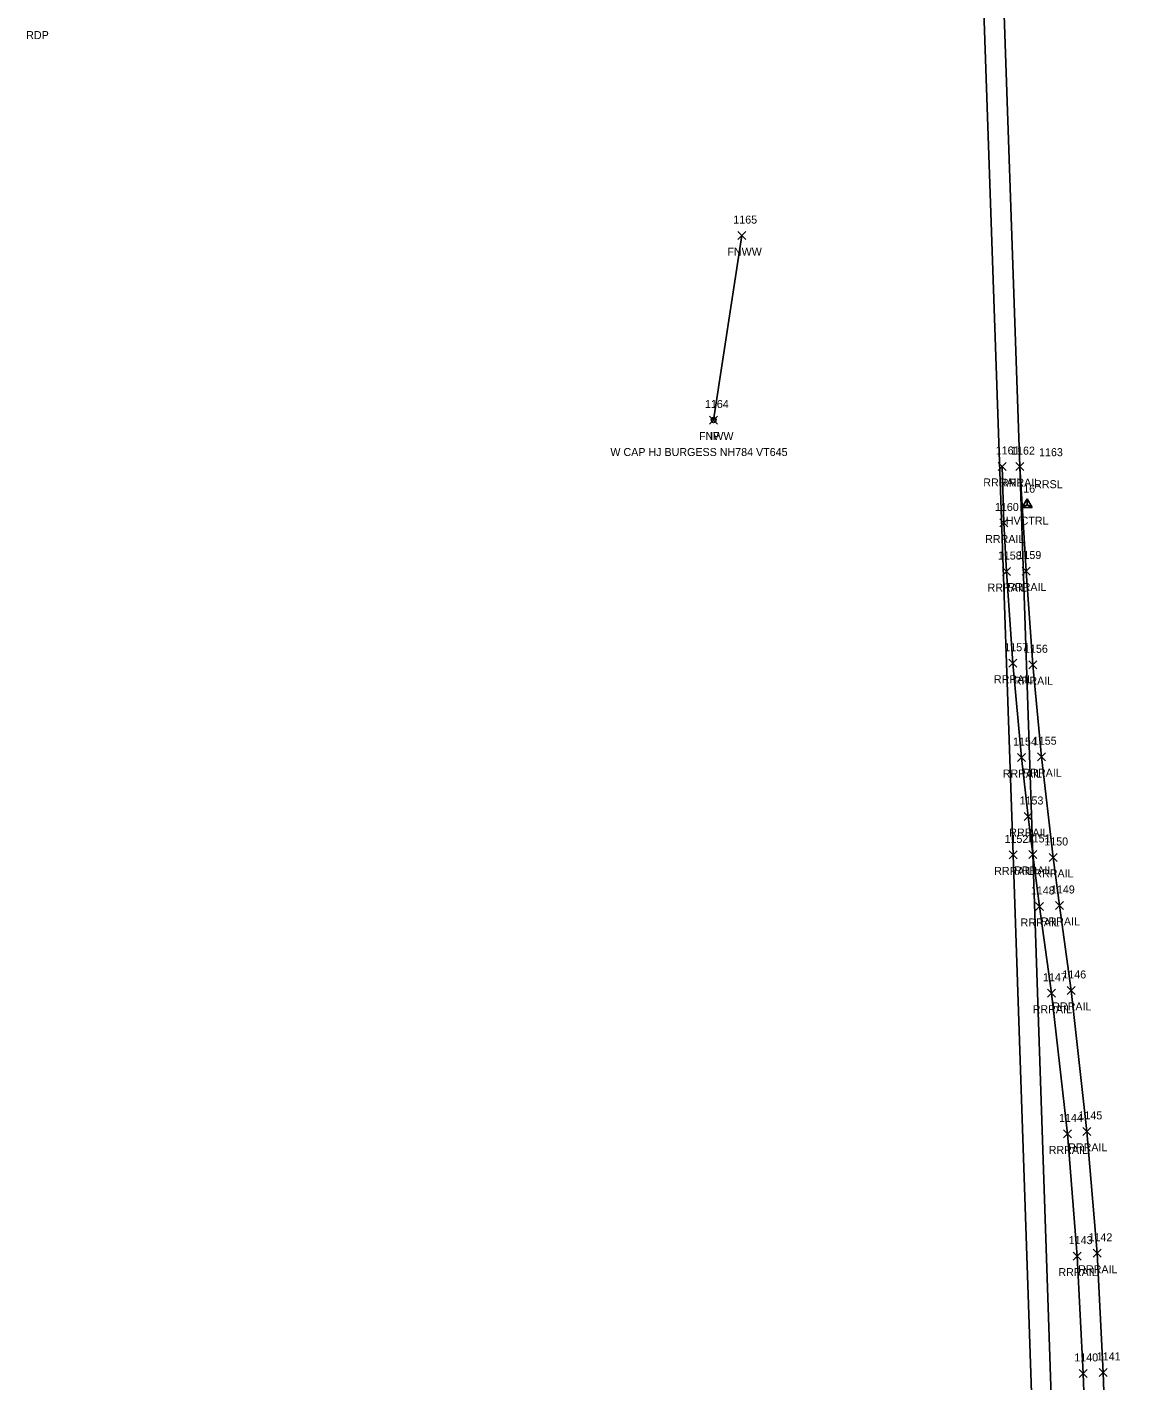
# Model space of a CAD drawing. Extents: x 1754529 to 1755810, y 621660 to 624656.
# Drawn here: x 1755390 to 1755667.2, y 622000 to 622338.3 of the extents above; entities that cross this region are included whole.
import ezdxf

# ---------------------------------------------------------------- set-up
doc = ezdxf.new("R2010")
doc.units = 0
for name, color, linetype in [('C_A', 7, 'Continuous'), ('C_I', 7, 'Continuous'), ('CPSM', 7, 'Continuous'), ('L_A', 7, 'Continuous'), ('L_I', 7, 'Continuous'), ('L_TIC', 7, 'Continuous'), ('LFNC', 7, 'Continuous'), ('M_A', 7, 'Continuous'), ('M_C', 7, 'Continuous'), ('M_I', 7, 'Continuous'), ('MPIR', 7, 'Continuous'), ('P_A', 7, 'Continuous'), ('R_A', 7, 'Continuous'), ('R_I', 7, 'Continuous'), ('R_TIC', 7, 'Continuous'), ('RR', 7, 'Continuous')]:
    doc.layers.add(name, color=color, linetype=linetype)

msp = doc.modelspace()

# ---------------------------------------------------------------- linework, layer by layer
at = {"layer": 'CPSM'}
for p, q in [((1755638.69, 622218.24), (1755639.94, 622220.41)), ((1755641.19, 622218.24), (1755639.94, 622220.41)), ((1755639.94, 622218.96), (1755639.94, 622220.41)), ((1755638.69, 622218.24), (1755639.94, 622218.96)), ((1755638.69, 622218.24), (1755641.19, 622218.24)), ((1755639.94, 622218.96), (1755639.94, 622218.96)), ((1755639.94, 622218.96), (1755641.19, 622218.24))]:
    msp.add_line(p, q, dxfattribs=at)
at = {"layer": 'L_TIC'}
for points in [[(1755567.69, 622285.2), (1755569.69, 622287.2)], [(1755569.69, 622285.2), (1755567.69, 622287.2)], [(1755560.6, 622239.12), (1755562.6, 622241.12)], [(1755562.6, 622239.12), (1755560.6, 622241.12)]]:
    msp.add_lwpolyline(points, dxfattribs=at)
at = {"layer": 'LFNC'}
msp.add_lwpolyline([(1755561.6, 622240.12), (1755568.69, 622286.2)], dxfattribs=at)
at = {"layer": 'MPIR'}
for radius in [0.625, 0.0833]:
    msp.add_circle((1755561.6, 622240.12), radius, dxfattribs=at)
at = {"layer": 'R_TIC'}
for points in [[(1755632.72, 622227.52), (1755634.72, 622229.52)], [(1755634.72, 622227.52), (1755632.72, 622229.52)], [(1755637.13, 622227.47), (1755639.13, 622229.47)], [(1755639.13, 622227.47), (1755637.13, 622229.47)], [(1755637.13, 622227.47), (1755639.13, 622229.47)], [(1755639.13, 622227.47), (1755637.13, 622229.47)], [(1755633.18, 622213.39), (1755635.18, 622215.39)], [(1755635.18, 622213.39), (1755633.18, 622215.39)], [(1755633.79, 622201.25), (1755635.79, 622203.25)], [(1755635.79, 622201.25), (1755633.79, 622203.25)], [(1755638.7, 622201.38), (1755640.7, 622203.38)], [(1755640.7, 622201.38), (1755638.7, 622203.38)], [(1755635.38, 622178.34), (1755637.38, 622180.34)], [(1755637.38, 622178.34), (1755635.38, 622180.34)], [(1755640.37, 622177.94), (1755642.37, 622179.94)], [(1755642.37, 622177.94), (1755640.37, 622179.94)], [(1755637.59, 622154.76), (1755639.59, 622156.76)], [(1755639.59, 622154.76), (1755637.59, 622156.76)], [(1755642.53, 622154.97), (1755644.53, 622156.97)], [(1755644.53, 622154.97), (1755642.53, 622156.97)], [(1755639.21, 622140.03), (1755641.21, 622142.03)], [(1755641.21, 622140.03), (1755639.21, 622142.03)], [(1755635.45, 622130.43), (1755637.45, 622132.43)], [(1755637.45, 622130.43), (1755635.45, 622132.43)], [(1755640.42, 622130.55), (1755642.42, 622132.55)], [(1755642.42, 622130.55), (1755640.42, 622132.55)], [(1755640.42, 622130.55), (1755642.42, 622132.55)], [(1755642.42, 622130.55), (1755640.42, 622132.55)], [(1755645.48, 622129.79), (1755647.48, 622131.79)], [(1755647.48, 622129.79), (1755645.48, 622131.79)], [(1755642.03, 622117.54), (1755644.03, 622119.54)], [(1755644.03, 622117.54), (1755642.03, 622119.54)], [(1755647.07, 622117.8), (1755649.07, 622119.8)], [(1755649.07, 622117.8), (1755647.07, 622119.8)], [(1755649.95, 622096.56), (1755651.95, 622098.56)], [(1755651.95, 622096.56), (1755649.95, 622098.56)], [(1755645.07, 622095.87), (1755647.07, 622097.87)], [(1755647.07, 622095.87), (1755645.07, 622097.87)], [(1755649.07, 622060.71), (1755651.07, 622062.71)], [(1755651.07, 622060.71), (1755649.07, 622062.71)], [(1755653.93, 622061.34), (1755655.93, 622063.34)], [(1755655.93, 622061.34), (1755653.93, 622063.34)], [(1755651.5, 622030.16), (1755653.5, 622032.16)], [(1755653.5, 622030.16), (1755651.5, 622032.16)], [(1755656.45, 622030.87), (1755658.45, 622032.87)], [(1755658.45, 622030.87), (1755656.45, 622032.87)], [(1755652.99, 622000.85), (1755654.99, 622002.85)], [(1755654.99, 622000.85), (1755652.99, 622002.85)], [(1755657.94, 622001.1), (1755659.94, 622003.1)], [(1755659.94, 622001.1), (1755657.94, 622003.1)]]:
    msp.add_lwpolyline(points, dxfattribs=at)
at = {"layer": 'RR'}
for points in [[(1755648.95, 621764.81), (1755636.45, 622131.43), (1755613.67, 622787.88), (1755609.16, 622923.97), (1755607.65, 622970.2), (1755606.39, 623016.18), (1755605.63, 623052.66), (1755604.97, 623087.09), (1755604.49, 623127.28), (1755604.22, 623170.71)], [(1755653.84, 621764.86), (1755641.42, 622131.55), (1755638.13, 622228.47), (1755618.69, 622787.98), (1755614.09, 622923.65), (1755612.57, 622970.4), (1755611.33, 623016.44), (1755610.51, 623052.88), (1755609.89, 623087.03), (1755609.4, 623127.16), (1755609.16, 623170.67)], [(1755662.28, 621764.64), (1755655.09, 621972.73), (1755653.99, 622001.85), (1755652.5, 622031.16), (1755650.07, 622061.71), (1755646.07, 622096.87), (1755643.03, 622118.54), (1755641.42, 622131.55), (1755640.21, 622141.03), (1755638.59, 622155.76), (1755636.38, 622179.34), (1755634.79, 622202.25), (1755634.18, 622214.39), (1755633.72, 622228.52)], [(1755667.17, 621764.34), (1755659.97, 621973.23), (1755658.94, 622002.1), (1755657.45, 622031.87), (1755654.93, 622062.34), (1755650.95, 622097.56), (1755648.07, 622118.8), (1755646.48, 622130.79), (1755643.53, 622155.97), (1755641.37, 622178.94), (1755639.7, 622202.38), (1755638.13, 622228.47)]]:
    msp.add_lwpolyline(points, dxfattribs=at)

# ---------------------------------------------------------------- texts
at = {"layer": 'C_A'}
msp.add_text('HVCTRL', height=2, dxfattribs=at).set_placement((1755634.63, 622213.96))
at = {"layer": 'C_I'}
msp.add_text('16', height=2, dxfattribs=at).set_placement((1755638.99, 622221.96))
at = {"layer": 'L_A'}
for p in [(1755565.04, 622281.2), (1755557.95, 622235.12)]:
    msp.add_text('FNWW', height=2, dxfattribs=at).set_placement(p)
at = {"layer": 'L_I'}
for s, p in [('1165', (1755566.52, 622289.2)), ('1164', (1755559.43, 622243.12))]:
    msp.add_text(s, height=2, dxfattribs=at).set_placement(p)
at = {"layer": 'M_A'}
msp.add_text('IP', height=2, dxfattribs=at).set_placement((1755560.65, 622235.12))
at = {"layer": 'M_C'}
msp.add_text('W CAP HJ BURGESS NH784 VT645', height=2, dxfattribs=at).set_placement((1755535.79, 622231.12))
at = {"layer": 'M_I'}
msp.add_text('1164', height=2, dxfattribs=at).set_placement((1755559.43, 622243.12))
at = {"layer": 'P_A'}
msp.add_text('RDP', height=2, dxfattribs=at).set_placement((1755389.75, 622335.32))
at = {"layer": 'R_A'}
for s, p in [('RRRAIL', (1755629.01, 622223.52)), ('RRRAIL', (1755633.42, 622223.47)), ('RRRAIL', (1755633.42, 622223.47)), ('RRSL', (1755641.72, 622223.08)), ('RRRAIL', (1755629.47, 622209.39)), ('RRRAIL', (1755630.08, 622197.25)), ('RRRAIL', (1755634.99, 622197.38)), ('RRRAIL', (1755631.67, 622174.34)), ('RRRAIL', (1755636.66, 622173.94)), ('RRRAIL', (1755633.88, 622150.76)), ('RRRAIL', (1755638.82, 622150.97)), ('RRRAIL', (1755635.5, 622136.03)), ('RRRAIL', (1755631.74, 622126.43)), ('RRRAIL', (1755636.71, 622126.55)), ('RRRAIL', (1755636.71, 622126.55)), ('RRRAIL', (1755641.77, 622125.79)), ('RRRAIL', (1755638.33, 622113.54)), ('RRRAIL', (1755643.36, 622113.8)), ('RRRAIL', (1755641.36, 622091.87)), ('RRRAIL', (1755646.24, 622092.56)), ('RRRAIL', (1755645.36, 622056.71)), ('RRRAIL', (1755650.23, 622057.34)), ('RRRAIL', (1755647.79, 622026.16)), ('RRRAIL', (1755652.74, 622026.87))]:
    msp.add_text(s, height=2, dxfattribs=at).set_placement(p)
at = {"layer": 'R_I'}
for s, p in [('1161', (1755632.11, 622231.52)), ('1162', (1755635.96, 622231.47)), ('1162', (1755635.96, 622231.47)), ('1163', (1755642.95, 622231.08)), ('1160', (1755631.92, 622217.39)), ('1158', (1755632.66, 622205.25)), ('1159', (1755637.56, 622205.38)), ('1157', (1755634.25, 622182.34)), ('1156', (1755639.19, 622181.94)), ('1154', (1755636.46, 622158.76)), ('1155', (1755641.4, 622158.97)), ('1153', (1755638.08, 622144.03)), ('1152', (1755634.32, 622134.43)), ('1151', (1755639.86, 622134.55)), ('1151', (1755639.86, 622134.55)), ('1150', (1755644.27, 622133.79)), ('1148', (1755640.91, 622121.54)), ('1149', (1755645.93, 622121.8)), ('1147', (1755643.94, 622099.87)), ('1146', (1755648.77, 622100.56)), ('1144', (1755647.95, 622064.71)), ('1145', (1755652.81, 622065.34)), ('1143', (1755650.37, 622034.16)), ('1142', (1755655.32, 622034.87)), ('1141', (1755657.38, 622005.1)), ('1140', (1755651.77, 622004.85))]:
    msp.add_text(s, height=2, dxfattribs=at).set_placement(p)

doc.saveas('drawing.dxf')
